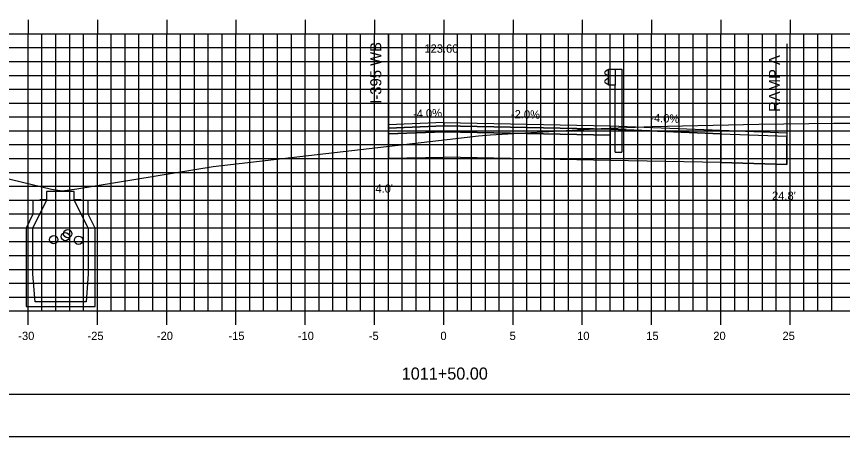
# Model space of a CAD drawing. Extents: x 852404 to 852575, y 365624 to 365734.
# Drawn here: x 852456 to 852515.6, y 365624 to 365654.3 of the extents above; entities that cross this region are included whole.
import ezdxf

# ---------------------------------------------------------------- set-up
doc = ezdxf.new("R2010")
doc.units = 0
for name, color, linetype in [('ANNOTATION', 7, 'Continuous'), ('BORDER', 7, 'Continuous'), ('D_Roadway_Centerline', 7, 'Continuous'), ('D_Roadway_Centerline_Text', 7, 'Continuous'), ('D_Roadway_Edge_Shoulder', 7, 'Continuous'), ('D_Roadway_Edge_TW', 7, 'Continuous'), ('D_Roadway_FinishedGrade', 7, 'Continuous'), ('D_Roadway_Pavement', 7, 'Continuous'), ('D_Roadway_SubGrade', 7, 'Continuous'), ('D_Text_Standard', 7, 'Continuous'), ('Default', 7, 'Continuous'), ('H_V ANNOTATION', 7, 'Continuous'), ('M_Guardrail', 7, 'Continuous'), ('MAJOR', 7, 'Continuous'), ('MINOR', 7, 'Continuous'), ('PLOT BOUNDARY', 7, 'Continuous'), ('S_Drainage_CB', 7, 'Continuous'), ('S_Drainage_Invert', 7, 'Continuous'), ('S_Roadway_Centerline', 7, 'Continuous')]:
    doc.layers.add(name, color=color, linetype=linetype)

msp = doc.modelspace()

# ---------------------------------------------------------------- linework, layer by layer
at = {"layer": 'BORDER'}
msp.add_lwpolyline([(852411.792, 365627.027), (852571.792, 365627.027), (852571.792, 365732.027), (852411.792, 365732.027)], close=True, dxfattribs=at)
at = {"layer": 'D_Roadway_Centerline'}
for p, q in [((852506.791, 365646.069), (852511.564, 365645.878)), ((852506.791, 365645.819), (852511.564, 365645.628)), ((852506.791, 365643.729), (852511.563, 365643.586))]:
    msp.add_line(p, q, dxfattribs=at)
at = {"layer": 'D_Roadway_Edge_Shoulder'}
for points in [[(852486.792, 365646.629), (852482.791, 365646.469), (852482.791, 365646.219), (852486.792, 365646.379)], [(852498.792, 365646.389), (852506.791, 365646.069), (852506.791, 365645.819), (852498.792, 365646.139)]]:
    msp.add_lwpolyline(points, close=True, dxfattribs=at)
at = {"layer": 'D_Roadway_Edge_TW'}
msp.add_lwpolyline([(852486.792, 365646.629), (852498.792, 365646.389), (852498.792, 365646.139), (852486.792, 365646.379)], close=True, dxfattribs=at)
msp.add_lwpolyline([(852498.792, 365646.389), (852498.792, 365646.222)], dxfattribs=at)
at = {"layer": 'D_Roadway_FinishedGrade'}
for p, q in [((852482.791, 365646.469), (852482.791, 365646.219)), ((852486.792, 365646.629), (852486.792, 365646.379)), ((852498.792, 365646.389), (852498.792, 365646.139)), ((852506.791, 365646.069), (852506.791, 365645.819)), ((852506.791, 365646.069), (852506.791, 365645.819)), ((852511.564, 365645.807), (852511.564, 365645.557))]:
    msp.add_line(p, q, dxfattribs=at)
at = {"layer": 'D_Roadway_Pavement'}
for points in [[(852486.792, 365646.379), (852482.791, 365646.219), (852482.791, 365645.802), (852486.792, 365645.962)], [(852486.792, 365646.379), (852498.792, 365646.139), (852498.792, 365645.722), (852486.792, 365645.962)]]:
    msp.add_lwpolyline(points, close=True, dxfattribs=at)
msp.add_lwpolyline([(852498.792, 365646.222), (852498.792, 365645.722)], dxfattribs=at)
msp.add_lwpolyline([(852498.792, 365646.222), (852498.792, 365645.722)], dxfattribs=at)
at = {"layer": 'D_Roadway_SubGrade'}
for p, q in [((852482.791, 365652.966), (852482.791, 365644.049)), ((852511.564, 365652.304), (852511.564, 365643.586))]:
    msp.add_line(p, q, dxfattribs=at)
for points in [[(852486.792, 365645.962), (852482.791, 365645.802), (852482.791, 365646.302), (852482.791, 365646.469), (852482.791, 365644.049), (852486.792, 365644.129)], [(852486.792, 365645.962), (852498.792, 365645.722), (852498.792, 365643.889), (852486.792, 365644.129)], [(852498.792, 365645.722), (852498.792, 365646.139), (852506.791, 365645.819), (852506.791, 365646.069), (852506.791, 365643.729), (852498.792, 365643.889)]]:
    msp.add_lwpolyline(points, close=True, dxfattribs=at)
for points in [[(852498.792, 365645.722), (852498.792, 365643.889)], [(852511.563, 365643.586), (852511.563, 365643.836), (852511.563, 365645.557)]]:
    msp.add_lwpolyline(points, dxfattribs=at)
at = {"layer": 'Default'}
msp.add_lwpolyline([(852511.563, 365643.586), (852506.791, 365643.729)], dxfattribs=at)
at = {"layer": 'M_Guardrail'}
for p, q in [((852498.576, 365650.392), (852498.433, 365650.292)), ((852498.433, 365650.149), (852498.628, 365650.013)), ((852498.675, 365650.413), (852498.593, 365650.399)), ((852498.662, 365649.948), (852498.662, 365649.857)), ((852498.675, 365650.486), (852499.164, 365650.486)), ((852498.675, 365649.32), (852498.675, 365650.486)), ((852499.164, 365650.486), (852499.656, 365650.486)), ((852499.164, 365650.486), (852499.164, 365649.32)), ((852499.656, 365650.486), (852499.656, 365644.486)), ((852498.628, 365649.793), (852498.433, 365649.657)), ((852498.433, 365649.514), (852498.576, 365649.414)), ((852498.593, 365649.407), (852498.675, 365649.392)), ((852499.164, 365649.32), (852498.675, 365649.32)), ((852499.164, 365644.486), (852499.164, 365649.32)), ((852499.164, 365644.486), (852499.656, 365644.486))]:
    msp.add_line(p, q, dxfattribs=at)
for centre, major_axis, start_param, end_param in [((852498.483, 365650.221), (-0.0877, 0), 5.323254, 7.243116), ((852498.6, 365650.358), (-0.0417, 0), 4.886922, 5.323254), ((852498.583, 365649.948), (0.0789, 0), 0, 0.959931), ((852498.483, 365649.585), (-0.0877, 0), 5.323254, 7.243116), ((852498.6, 365649.448), (-0.0417, 0), 0.959931, 1.396263), ((852498.583, 365649.857), (0.0789, 0), 5.323254, 6.283185)]:
    msp.add_ellipse(centre, major_axis=major_axis, ratio=0.995501, start_param=start_param, end_param=end_param, dxfattribs=at)
at = {"layer": 'MAJOR'}
for p, q in [((852456.792, 365654.029), (852456.792, 365653.027)), ((852461.792, 365654.029), (852461.792, 365653.027)), ((852466.792, 365654.029), (852466.792, 365653.027)), ((852471.792, 365654.029), (852471.792, 365653.027)), ((852476.792, 365654.029), (852476.792, 365653.027)), ((852481.792, 365654.029), (852481.792, 365653.027)), ((852486.792, 365654.029), (852486.792, 365653.027)), ((852491.792, 365654.029), (852491.792, 365653.027)), ((852496.792, 365654.029), (852496.792, 365653.027)), ((852501.792, 365654.029), (852501.792, 365653.027)), ((852506.792, 365654.029), (852506.792, 365653.027)), ((852511.792, 365654.029), (852511.792, 365653.027)), ((852416.792, 365653.027), (852556.792, 365653.027)), ((852416.792, 365653.027), (852556.792, 365653.027)), ((852456.792, 365633.027), (852456.792, 365653.027)), ((852461.792, 365633.027), (852461.792, 365653.027)), ((852466.792, 365633.027), (852466.792, 365653.027)), ((852471.792, 365633.027), (852471.792, 365653.027)), ((852476.792, 365633.027), (852476.792, 365653.027)), ((852481.792, 365633.027), (852481.792, 365653.027)), ((852486.792, 365633.027), (852486.792, 365653.027)), ((852491.792, 365633.027), (852491.792, 365653.027)), ((852496.792, 365633.027), (852496.792, 365653.027)), ((852501.792, 365633.027), (852501.792, 365653.027)), ((852506.792, 365633.027), (852506.792, 365653.027)), ((852511.792, 365633.027), (852511.792, 365653.027)), ((852416.792, 365648.027), (852556.792, 365648.027)), ((852416.792, 365643.027), (852556.792, 365643.027)), ((852416.792, 365638.027), (852556.792, 365638.027)), ((852416.792, 365633.027), (852556.792, 365633.027)), ((852416.792, 365633.027), (852556.792, 365633.027)), ((852456.792, 365632.025), (852456.792, 365633.027)), ((852461.792, 365632.025), (852461.792, 365633.027)), ((852466.792, 365632.025), (852466.792, 365633.027)), ((852471.792, 365632.025), (852471.792, 365633.027)), ((852476.792, 365632.025), (852476.792, 365633.027)), ((852481.792, 365632.025), (852481.792, 365633.027)), ((852486.792, 365632.025), (852486.792, 365633.027)), ((852491.792, 365632.025), (852491.792, 365633.027)), ((852496.792, 365632.025), (852496.792, 365633.027)), ((852501.792, 365632.025), (852501.792, 365633.027)), ((852506.792, 365632.025), (852506.792, 365633.027)), ((852511.792, 365632.025), (852511.792, 365633.027))]:
    msp.add_line(p, q, dxfattribs=at)
at = {"layer": 'MINOR'}
for p, q in [((852457.792, 365633.027), (852457.792, 365653.027)), ((852458.792, 365633.027), (852458.792, 365653.027)), ((852459.792, 365633.027), (852459.792, 365653.027)), ((852460.792, 365633.027), (852460.792, 365653.027)), ((852462.792, 365633.027), (852462.792, 365653.027)), ((852463.792, 365633.027), (852463.792, 365653.027)), ((852464.792, 365633.027), (852464.792, 365653.027)), ((852465.792, 365633.027), (852465.792, 365653.027)), ((852467.792, 365633.027), (852467.792, 365653.027)), ((852468.792, 365633.027), (852468.792, 365653.027)), ((852469.792, 365633.027), (852469.792, 365653.027)), ((852470.792, 365633.027), (852470.792, 365653.027)), ((852472.792, 365633.027), (852472.792, 365653.027)), ((852473.792, 365633.027), (852473.792, 365653.027)), ((852474.792, 365633.027), (852474.792, 365653.027)), ((852475.792, 365633.027), (852475.792, 365653.027)), ((852477.792, 365633.027), (852477.792, 365653.027)), ((852478.792, 365633.027), (852478.792, 365653.027)), ((852479.792, 365633.027), (852479.792, 365653.027)), ((852480.792, 365633.027), (852480.792, 365653.027)), ((852482.792, 365633.027), (852482.792, 365653.027)), ((852483.792, 365633.027), (852483.792, 365653.027)), ((852484.792, 365633.027), (852484.792, 365653.027)), ((852485.792, 365633.027), (852485.792, 365653.027)), ((852487.792, 365633.027), (852487.792, 365653.027)), ((852488.792, 365633.027), (852488.792, 365653.027)), ((852489.792, 365633.027), (852489.792, 365653.027)), ((852490.792, 365633.027), (852490.792, 365653.027)), ((852492.792, 365633.027), (852492.792, 365653.027)), ((852493.792, 365633.027), (852493.792, 365653.027)), ((852494.792, 365633.027), (852494.792, 365653.027)), ((852495.792, 365633.027), (852495.792, 365653.027)), ((852497.792, 365633.027), (852497.792, 365653.027)), ((852498.792, 365633.027), (852498.792, 365653.027)), ((852499.792, 365633.027), (852499.792, 365653.027)), ((852500.792, 365633.027), (852500.792, 365653.027)), ((852502.792, 365633.027), (852502.792, 365653.027)), ((852503.792, 365633.027), (852503.792, 365653.027)), ((852504.792, 365633.027), (852504.792, 365653.027)), ((852505.792, 365633.027), (852505.792, 365653.027)), ((852507.792, 365633.027), (852507.792, 365653.027)), ((852508.792, 365633.027), (852508.792, 365653.027)), ((852509.792, 365633.027), (852509.792, 365653.027)), ((852510.792, 365633.027), (852510.792, 365653.027)), ((852512.792, 365633.027), (852512.792, 365653.027)), ((852513.792, 365633.027), (852513.792, 365653.027)), ((852514.792, 365633.027), (852514.792, 365653.027)), ((852416.792, 365652.027), (852556.792, 365652.027)), ((852416.792, 365651.027), (852556.792, 365651.027)), ((852416.792, 365650.027), (852556.792, 365650.027)), ((852416.792, 365649.027), (852556.792, 365649.027)), ((852416.792, 365647.027), (852556.792, 365647.027)), ((852416.792, 365646.027), (852556.792, 365646.027)), ((852416.792, 365645.027), (852556.792, 365645.027)), ((852416.792, 365644.027), (852556.792, 365644.027)), ((852416.792, 365642.027), (852556.792, 365642.027)), ((852416.792, 365641.027), (852556.792, 365641.027)), ((852416.792, 365640.027), (852556.792, 365640.027)), ((852416.792, 365639.027), (852556.792, 365639.027)), ((852416.792, 365637.027), (852556.792, 365637.027)), ((852416.792, 365636.027), (852556.792, 365636.027)), ((852416.792, 365635.027), (852556.792, 365635.027)), ((852416.792, 365634.027), (852556.792, 365634.027))]:
    msp.add_line(p, q, dxfattribs=at)
at = {"layer": 'PLOT BOUNDARY'}
msp.add_lwpolyline([(852403.699, 365623.968), (852573.699, 365623.968), (852573.699, 365733.968), (852403.699, 365733.968)], close=True, dxfattribs=at)
at = {"layer": 'S_Drainage_CB'}
for p, q in [((852458.117, 365640.992), (852457.133, 365640.992)), ((852457.133, 365640.992), (852457.133, 365640.008)), ((852457.133, 365638.99), (852458.117, 365640.992)), ((852461.136, 365640.992), (852460.119, 365640.992)), ((852460.119, 365640.992), (852461.136, 365638.99)), ((852461.136, 365640.008), (852461.136, 365640.992)), ((852457.133, 365640.008), (852456.641, 365638.99)), ((852461.628, 365638.99), (852461.136, 365640.008)), ((852456.641, 365638.99), (852456.641, 365633.347)), ((852457.133, 365635.677), (852457.133, 365638.99)), ((852461.136, 365638.99), (852461.136, 365635.677)), ((852461.628, 365633.347), (852461.628, 365638.99)), ((852457.297, 365633.676), (852457.133, 365635.677)), ((852461.136, 365635.677), (852460.972, 365633.676)), ((852456.641, 365633.347), (852461.628, 365633.347)), ((852460.972, 365633.676), (852457.297, 365633.676))]:
    msp.add_line(p, q, dxfattribs=at)
msp.add_lwpolyline([(852460.611, 365641.033), (852460.119, 365641.033), (852460.119, 365641.657), (852458.117, 365641.657), (852458.117, 365641.033), (852457.625, 365641.033)], dxfattribs=at)
at = {"layer": 'S_Drainage_Invert'}
for centre in [(852459.48, 365638.39), (852459.653, 365638.603), (852458.644, 365638.173), (852460.429, 365638.131)]:
    msp.add_circle(centre, 0.3, dxfattribs=at)
at = {"layer": 'S_Roadway_Centerline'}
msp.add_lwpolyline([(852416.792, 365646.715), (852417.422, 365646.737), (852417.669, 365646.696), (852419.586, 365646.661), (852431.319, 365646.353), (852431.703, 365646.343), (852433.057, 365646.266), (852440.933, 365645.202), (852444.1, 365644.849), (852451.991, 365643.386), (852458.479, 365641.826), (852459.26, 365641.695), (852460.303, 365641.832), (852470.146, 365643.445), (852487.044, 365645.393), (852489.292, 365645.663), (852490.156, 365645.728), (852498.157, 365646.181), (852501.835, 365646.33), (852509.522, 365646.508), (852514.953, 365646.571), (852516.292, 365646.575)], dxfattribs=at)

# ---------------------------------------------------------------- texts
at = {"layer": 'ANNOTATION'}
for s, height, rotation, p in [('I-395 WB', 0.8, 90, (852482.285, 365647.976)), ('RAMP A', 0.8, 90, (852511.057, 365647.388)), ('-4.0%', 0.6, 2.29045, (852484.583, 365646.941)), ('-2.0%', 0.6, 358.85423, (852491.634, 365646.932)), ('-4.0%', 0.6, 357.70931, (852501.687, 365646.674))]:
    msp.add_text(s, height=height, rotation=rotation, dxfattribs=at).set_placement(p)
at = {"layer": 'D_Roadway_Centerline'}
for s, p in [('C', (852486.786, 365646.629)), ('L', (852486.792, 365646.621))]:
    msp.add_text(s, height=0.0146, dxfattribs=at).set_placement(p)
at = {"layer": 'D_Roadway_Centerline_Text'}
msp.add_text('123.60', height=0.6, dxfattribs=at).set_placement((852485.395, 365651.661))
at = {"layer": 'D_Text_Standard'}
for s, p in [("4.0'", (852481.858, 365641.557)), ("24.8'", (852510.486, 365641.039))]:
    msp.add_text(s, height=0.6, dxfattribs=at).set_placement(p)
at = {"layer": 'H_V ANNOTATION'}
for s, height, p in [('-30', 0.6, (852456.08, 365630.927)), ('-25', 0.6, (852461.077, 365630.927)), ('-20', 0.6, (852466.085, 365630.927)), ('-15', 0.6, (852471.249, 365630.927)), ('-10', 0.6, (852476.257, 365630.927)), ('-5', 0.6, (852481.382, 365630.927)), ('0', 0.6, (852486.551, 365630.927)), ('5', 0.6, (852491.543, 365630.927)), ('10', 0.6, (852496.417, 365630.927)), ('15', 0.6, (852501.409, 365630.927)), ('20', 0.6, (852506.246, 365630.927)), ('25', 0.6, (852511.238, 365630.927)), ('1011+50.00', 0.875, (852483.757, 365628.07))]:
    msp.add_text(s, height=height, dxfattribs=at).set_placement(p)

doc.saveas('drawing.dxf')
